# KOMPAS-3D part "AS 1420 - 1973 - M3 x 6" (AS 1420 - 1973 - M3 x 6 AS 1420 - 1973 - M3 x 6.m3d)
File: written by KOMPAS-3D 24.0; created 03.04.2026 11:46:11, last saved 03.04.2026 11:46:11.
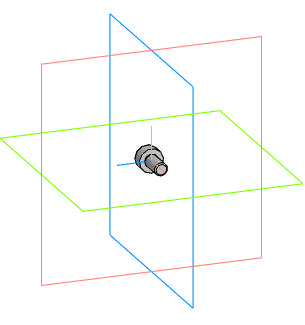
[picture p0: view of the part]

Document properties: Автор: R2D2; Полное имя файла: E:\Работа\Зайцев\Аксессуары для пневмоприводов\Ручной дублер DN.ru\MON1-250-T26-ISO Ручной дублер DN.ru\исходные материалы\AS 1420 - 1973 - M3 x 6 AS 1420 - 1973 - M3 x 6.m3d

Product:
- Body: Solid1  | qty 1
- Part/product: AS 1420 - 1973 - M3 x 6
    Комментарий: Винты с шестигранным   углублением метрические   ISO
    additional columns: Сталь, мягкая

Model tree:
1. Solid1  (labels: Solid1)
